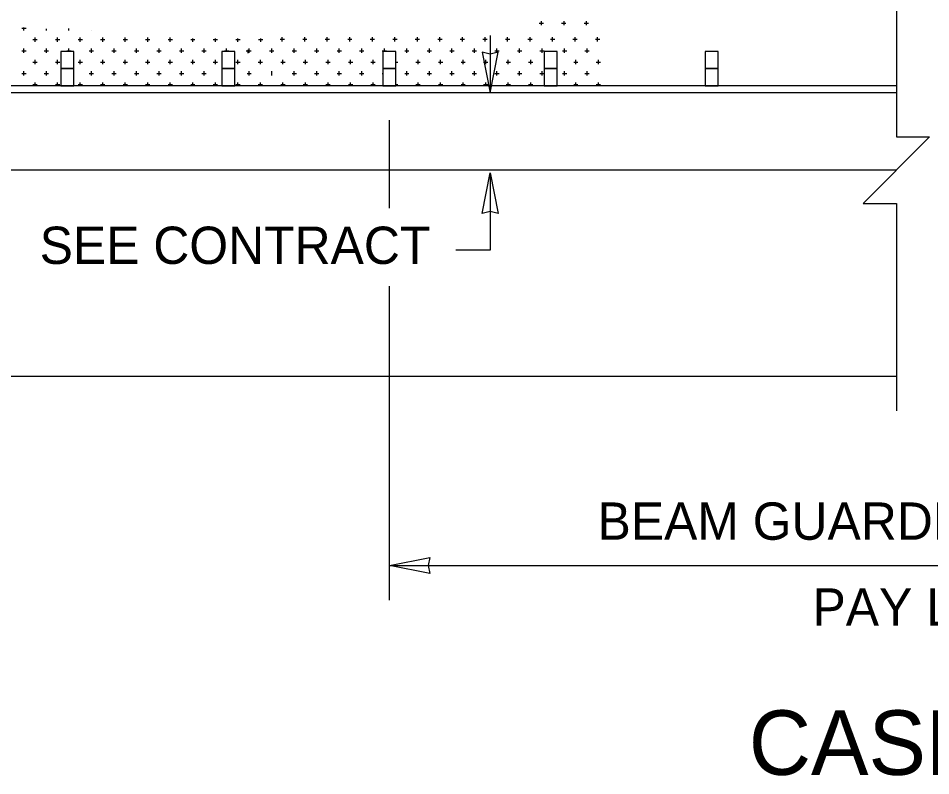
# Model space of a CAD drawing. Extents: x 1312564.5 to 1312581.5, y 1207298.4 to 1207309.4.
# Drawn here: x 1312568.156 to 1312570.114, y 1207305.016 to 1207306.641 of the extents above; entities that cross this region are included whole.
import ezdxf

# ---------------------------------------------------------------- set-up
doc = ezdxf.new("R2010")
doc.units = 0
for name, color, linetype in [('Level 1', 7, 'Continuous'), ('Level 15', 7, 'Continuous'), ('Level 2', 7, 'Continuous'), ('Level 20', 7, 'Continuous'), ('Level 3', 7, 'Continuous'), ('Level 4', 7, 'Continuous'), ('Level 44', 7, 'Continuous')]:
    doc.layers.add(name, color=color, linetype=linetype)

msp = doc.modelspace()

# ---------------------------------------------------------------- linework, layer by layer
at = {"layer": 'Level 15'}
for p, q in [((1312569.1684, 1207306.6036), (1312569.1684, 1207306.4809)), ((1312569.1684, 1207306.309), (1312569.1684, 1207306.1431)), ((1312569.1684, 1207306.1431), (1312569.0946, 1207306.1431))]:
    msp.add_line(p, q, dxfattribs=at)
for points in [[(1312570.0398, 1207306.8953), (1312570.0398, 1207306.3861), (1312570.1112, 1207306.3861), (1312569.9685, 1207306.2434), (1312570.0398, 1207306.2434), (1312570.0398, 1207305.7986)], [(1312568.9523, 1207306.2332), (1312568.9523, 1207306.4221)], [(1312568.9523, 1207305.3931), (1312568.9523, 1207306.0659)], [(1312568.9523, 1207305.4668), (1312571.2748, 1207305.4668)]]:
    msp.add_lwpolyline(points, dxfattribs=at)
for points in [[(1312569.1684, 1207306.4809), (1312569.1854, 1207306.5679), (1312569.1684, 1207306.5638), (1312569.1513, 1207306.5679)], [(1312569.1684, 1207306.309), (1312569.1854, 1207306.2221), (1312569.1684, 1207306.2261), (1312569.1513, 1207306.2221)], [(1312568.9523, 1207305.4668), (1312569.0393, 1207305.4839), (1312569.0353, 1207305.4668), (1312569.0393, 1207305.4498)]]:
    msp.add_lwpolyline(points, close=True, dxfattribs=at)
at = {"layer": 'Level 2'}
for p, q in [((1312570.0398, 1207306.4959), (1312566.8787, 1207306.4959)), ((1312570.0398, 1207306.4806), (1312566.8787, 1207306.4806))]:
    msp.add_line(p, q, dxfattribs=at)
for points in [[(1312568.2473, 1207306.5327), (1312568.275, 1207306.5327), (1312568.275, 1207306.5696), (1312568.2473, 1207306.5696)], [(1312568.5929, 1207306.5327), (1312568.6206, 1207306.5327), (1312568.6206, 1207306.5696), (1312568.5929, 1207306.5696)], [(1312568.9385, 1207306.5327), (1312568.9662, 1207306.5327), (1312568.9662, 1207306.5696), (1312568.9385, 1207306.5696)], [(1312569.2841, 1207306.5327), (1312569.3118, 1207306.5327), (1312569.3118, 1207306.5696), (1312569.2841, 1207306.5696)], [(1312569.6297, 1207306.5327), (1312569.6574, 1207306.5327), (1312569.6574, 1207306.5696), (1312569.6297, 1207306.5696)], [(1312568.2473, 1207306.4959), (1312568.275, 1207306.4959), (1312568.275, 1207306.5327), (1312568.2473, 1207306.5327)], [(1312568.5929, 1207306.4959), (1312568.6206, 1207306.4959), (1312568.6206, 1207306.5327), (1312568.5929, 1207306.5327)], [(1312568.9385, 1207306.4959), (1312568.9662, 1207306.4959), (1312568.9662, 1207306.5327), (1312568.9385, 1207306.5327)], [(1312569.2841, 1207306.4959), (1312569.3118, 1207306.4959), (1312569.3118, 1207306.5327), (1312569.2841, 1207306.5327)], [(1312569.6297, 1207306.4959), (1312569.6574, 1207306.4959), (1312569.6574, 1207306.5327), (1312569.6297, 1207306.5327)]]:
    msp.add_lwpolyline(points, close=True, dxfattribs=at)
at = {"layer": 'Level 3'}
msp.add_line((1312570.0398, 1207306.3147), (1312565.7882, 1207306.3147), dxfattribs=at)
at = {"layer": 'Level 4'}
for p, q in [((1312569.2734, 1207306.63), (1312569.2826, 1207306.63)), ((1312569.278, 1207306.6346), (1312569.278, 1207306.6254)), ((1312569.3217, 1207306.63), (1312569.3263, 1207306.63)), ((1312569.3263, 1207306.6346), (1312569.3263, 1207306.6254)), ((1312569.3263, 1207306.63), (1312569.3309, 1207306.63)), ((1312569.3701, 1207306.63), (1312569.3793, 1207306.63)), ((1312569.3747, 1207306.6346), (1312569.3747, 1207306.6254)), ((1312568.1635, 1207306.6191), (1312568.1728, 1207306.6191)), ((1312568.1682, 1207306.6145), (1312568.1682, 1207306.6208)), ((1312568.2165, 1207306.6145), (1312568.2165, 1207306.6177)), ((1312568.2648, 1207306.6145), (1312568.2648, 1207306.6185)), ((1312568.3131, 1207306.6145), (1312568.3131, 1207306.6145)), ((1312568.1877, 1207306.5949), (1312568.1923, 1207306.5949)), ((1312568.1923, 1207306.5903), (1312568.1923, 1207306.5995)), ((1312568.1923, 1207306.5949), (1312568.1969, 1207306.5949)), ((1312568.236, 1207306.5949), (1312568.2452, 1207306.5949)), ((1312568.2406, 1207306.5903), (1312568.2406, 1207306.5995)), ((1312568.2844, 1207306.5949), (1312568.2936, 1207306.5949)), ((1312568.289, 1207306.5903), (1312568.289, 1207306.5995)), ((1312568.3327, 1207306.5949), (1312568.3419, 1207306.5949)), ((1312568.3373, 1207306.5903), (1312568.3373, 1207306.5995)), ((1312568.381, 1207306.5949), (1312568.3902, 1207306.5949)), ((1312568.3856, 1207306.5903), (1312568.3856, 1207306.5995)), ((1312568.4293, 1207306.5949), (1312568.4386, 1207306.5949)), ((1312568.4339, 1207306.5903), (1312568.4339, 1207306.5995)), ((1312568.4777, 1207306.5949), (1312568.4823, 1207306.5949)), ((1312568.4823, 1207306.5903), (1312568.4823, 1207306.5995)), ((1312568.4823, 1207306.5949), (1312568.4869, 1207306.5949)), ((1312568.526, 1207306.5949), (1312568.5352, 1207306.5949)), ((1312568.5306, 1207306.5903), (1312568.5306, 1207306.5971)), ((1312568.5743, 1207306.5949), (1312568.5835, 1207306.5949)), ((1312568.5789, 1207306.5903), (1312568.5789, 1207306.5971)), ((1312568.6226, 1207306.5949), (1312568.6319, 1207306.5949)), ((1312568.6273, 1207306.5903), (1312568.6273, 1207306.5971)), ((1312568.6714, 1207306.5949), (1312568.6807, 1207306.5949)), ((1312568.6761, 1207306.5903), (1312568.6761, 1207306.5971)), ((1312568.7178, 1207306.5955), (1312568.727, 1207306.5955)), ((1312568.7224, 1207306.5909), (1312568.7224, 1207306.6001)), ((1312568.7662, 1207306.5955), (1312568.7754, 1207306.5955)), ((1312568.7708, 1207306.5909), (1312568.7708, 1207306.6001)), ((1312568.8145, 1207306.5955), (1312568.8237, 1207306.5955)), ((1312568.8191, 1207306.5909), (1312568.8191, 1207306.6001)), ((1312568.8628, 1207306.5955), (1312568.872, 1207306.5955)), ((1312568.8674, 1207306.5909), (1312568.8674, 1207306.6001)), ((1312568.9111, 1207306.5955), (1312568.9203, 1207306.5955)), ((1312568.9157, 1207306.5909), (1312568.9157, 1207306.6001)), ((1312568.9595, 1207306.5955), (1312568.9687, 1207306.5955)), ((1312568.9641, 1207306.5909), (1312568.9641, 1207306.6001)), ((1312569.0078, 1207306.5955), (1312569.017, 1207306.5955)), ((1312569.0124, 1207306.5909), (1312569.0124, 1207306.6001)), ((1312569.0561, 1207306.5955), (1312569.0653, 1207306.5955)), ((1312569.0607, 1207306.5909), (1312569.0607, 1207306.6001)), ((1312569.1044, 1207306.5955), (1312569.1137, 1207306.5955)), ((1312569.109, 1207306.5909), (1312569.109, 1207306.6001)), ((1312569.1528, 1207306.5955), (1312569.162, 1207306.5955)), ((1312569.1574, 1207306.5909), (1312569.1574, 1207306.6001)), ((1312569.2011, 1207306.5955), (1312569.2103, 1207306.5955)), ((1312569.2057, 1207306.5909), (1312569.2057, 1207306.6001)), ((1312569.2494, 1207306.5955), (1312569.2586, 1207306.5955)), ((1312569.254, 1207306.5909), (1312569.254, 1207306.6001)), ((1312569.2978, 1207306.5955), (1312569.307, 1207306.5955)), ((1312569.3024, 1207306.5909), (1312569.3024, 1207306.6001)), ((1312569.3461, 1207306.5955), (1312569.3553, 1207306.5955)), ((1312569.3507, 1207306.5909), (1312569.3507, 1207306.6001)), ((1312569.3944, 1207306.5955), (1312569.4036, 1207306.5955)), ((1312569.399, 1207306.5909), (1312569.399, 1207306.6001)), ((1312568.1635, 1207306.5708), (1312568.1728, 1207306.5708)), ((1312568.1682, 1207306.5662), (1312568.1682, 1207306.5754)), ((1312568.2119, 1207306.5708), (1312568.2211, 1207306.5708)), ((1312568.2165, 1207306.5662), (1312568.2165, 1207306.5754)), ((1312568.2602, 1207306.5708), (1312568.2694, 1207306.5708)), ((1312568.2648, 1207306.5696), (1312568.2648, 1207306.5754)), ((1312568.3085, 1207306.5708), (1312568.3177, 1207306.5708)), ((1312568.3131, 1207306.5662), (1312568.3131, 1207306.5754)), ((1312568.3568, 1207306.5708), (1312568.3661, 1207306.5708)), ((1312568.3615, 1207306.5662), (1312568.3615, 1207306.5754)), ((1312568.4052, 1207306.5708), (1312568.4144, 1207306.5708)), ((1312568.4098, 1207306.5662), (1312568.4098, 1207306.5754)), ((1312568.4535, 1207306.5708), (1312568.4627, 1207306.5708)), ((1312568.4581, 1207306.5662), (1312568.4581, 1207306.5754)), ((1312568.5018, 1207306.5708), (1312568.511, 1207306.5708)), ((1312568.5064, 1207306.5662), (1312568.5064, 1207306.5754)), ((1312568.5502, 1207306.5708), (1312568.5594, 1207306.5708)), ((1312568.5548, 1207306.5662), (1312568.5548, 1207306.5754)), ((1312568.5985, 1207306.5708), (1312568.6077, 1207306.5708)), ((1312568.6031, 1207306.5696), (1312568.6031, 1207306.5754)), ((1312568.645, 1207306.5705), (1312568.6542, 1207306.5705)), ((1312568.6468, 1207306.5708), (1312568.656, 1207306.5708)), ((1312568.6496, 1207306.5659), (1312568.6496, 1207306.5727)), ((1312568.6514, 1207306.5662), (1312568.6514, 1207306.5754)), ((1312568.6951, 1207306.5708), (1312568.7044, 1207306.5708)), ((1312568.6997, 1207306.5662), (1312568.6997, 1207306.5754)), ((1312568.7435, 1207306.5708), (1312568.7527, 1207306.5708)), ((1312568.7481, 1207306.5662), (1312568.7481, 1207306.5754)), ((1312568.7918, 1207306.5708), (1312568.801, 1207306.5708)), ((1312568.7964, 1207306.5662), (1312568.7964, 1207306.5754)), ((1312568.8401, 1207306.5708), (1312568.8493, 1207306.5708)), ((1312568.8447, 1207306.5662), (1312568.8447, 1207306.5754)), ((1312568.8884, 1207306.5708), (1312568.8977, 1207306.5708)), ((1312568.8931, 1207306.5662), (1312568.8931, 1207306.5754)), ((1312568.9368, 1207306.5708), (1312568.946, 1207306.5708)), ((1312568.9414, 1207306.5696), (1312568.9414, 1207306.5754)), ((1312568.9851, 1207306.5708), (1312568.9943, 1207306.5708)), ((1312568.9897, 1207306.5662), (1312568.9897, 1207306.5754)), ((1312569.0334, 1207306.5708), (1312569.0426, 1207306.5708)), ((1312569.038, 1207306.5662), (1312569.038, 1207306.5754)), ((1312569.0818, 1207306.5708), (1312569.091, 1207306.5708)), ((1312569.0864, 1207306.5662), (1312569.0864, 1207306.5754)), ((1312569.1301, 1207306.5708), (1312569.1393, 1207306.5708)), ((1312569.1347, 1207306.5662), (1312569.1347, 1207306.5754)), ((1312569.1784, 1207306.5708), (1312569.1876, 1207306.5708)), ((1312569.183, 1207306.5662), (1312569.183, 1207306.5754)), ((1312569.2267, 1207306.5708), (1312569.236, 1207306.5708)), ((1312569.2313, 1207306.5662), (1312569.2313, 1207306.5754)), ((1312569.2751, 1207306.5708), (1312569.2843, 1207306.5708)), ((1312569.2797, 1207306.5662), (1312569.2797, 1207306.5754)), ((1312569.3234, 1207306.5708), (1312569.3326, 1207306.5708)), ((1312569.328, 1207306.5662), (1312569.328, 1207306.5754)), ((1312569.3717, 1207306.5708), (1312569.3809, 1207306.5708)), ((1312569.3763, 1207306.5662), (1312569.3763, 1207306.5754)), ((1312568.1923, 1207306.542), (1312568.1923, 1207306.5512)), ((1312568.2406, 1207306.542), (1312568.2406, 1207306.5512)), ((1312568.289, 1207306.542), (1312568.289, 1207306.5512)), ((1312568.3373, 1207306.542), (1312568.3373, 1207306.5512)), ((1312568.3856, 1207306.542), (1312568.3856, 1207306.5512)), ((1312568.4339, 1207306.542), (1312568.4339, 1207306.5512)), ((1312568.4823, 1207306.542), (1312568.4823, 1207306.5512)), ((1312568.5306, 1207306.542), (1312568.5306, 1207306.5512)), ((1312568.5789, 1207306.542), (1312568.5789, 1207306.5512)), ((1312568.6273, 1207306.542), (1312568.6273, 1207306.5512)), ((1312568.6756, 1207306.542), (1312568.6756, 1207306.5512)), ((1312568.7239, 1207306.542), (1312568.7239, 1207306.5512)), ((1312568.7722, 1207306.542), (1312568.7722, 1207306.5512)), ((1312568.8206, 1207306.542), (1312568.8206, 1207306.5512)), ((1312568.8689, 1207306.542), (1312568.8689, 1207306.5512)), ((1312568.9172, 1207306.542), (1312568.9172, 1207306.5512)), ((1312569.0139, 1207306.542), (1312569.0139, 1207306.5512)), ((1312569.0622, 1207306.542), (1312569.0622, 1207306.5512)), ((1312569.1105, 1207306.542), (1312569.1105, 1207306.5512)), ((1312569.1589, 1207306.542), (1312569.1589, 1207306.5512)), ((1312569.2072, 1207306.542), (1312569.2072, 1207306.5512)), ((1312569.2555, 1207306.542), (1312569.2555, 1207306.5512)), ((1312569.3522, 1207306.542), (1312569.3522, 1207306.5512)), ((1312569.4005, 1207306.542), (1312569.4005, 1207306.5512)), ((1312568.1877, 1207306.5466), (1312568.1923, 1207306.5466)), ((1312568.1923, 1207306.5466), (1312568.1969, 1207306.5466)), ((1312568.236, 1207306.5466), (1312568.2452, 1207306.5466)), ((1312568.2844, 1207306.5466), (1312568.2936, 1207306.5466)), ((1312568.3327, 1207306.5466), (1312568.3419, 1207306.5466)), ((1312568.381, 1207306.5466), (1312568.3902, 1207306.5466)), ((1312568.4293, 1207306.5466), (1312568.4386, 1207306.5466)), ((1312568.4777, 1207306.5466), (1312568.4823, 1207306.5466)), ((1312568.4823, 1207306.5466), (1312568.4869, 1207306.5466)), ((1312568.526, 1207306.5466), (1312568.5352, 1207306.5466)), ((1312568.5743, 1207306.5466), (1312568.5835, 1207306.5466)), ((1312568.6226, 1207306.5466), (1312568.6319, 1207306.5466)), ((1312568.671, 1207306.5466), (1312568.6802, 1207306.5466)), ((1312568.7193, 1207306.5466), (1312568.7285, 1207306.5466)), ((1312568.7676, 1207306.5466), (1312568.7722, 1207306.5466)), ((1312568.7722, 1207306.5466), (1312568.7768, 1207306.5466)), ((1312568.816, 1207306.5466), (1312568.8252, 1207306.5466)), ((1312568.8643, 1207306.5466), (1312568.8735, 1207306.5466)), ((1312568.9126, 1207306.5466), (1312568.9218, 1207306.5466)), ((1312568.9662, 1207306.5466), (1312568.9702, 1207306.5466)), ((1312569.0093, 1207306.5466), (1312569.0185, 1207306.5466)), ((1312569.0576, 1207306.5466), (1312569.0622, 1207306.5466)), ((1312569.0622, 1207306.5466), (1312569.0668, 1207306.5466)), ((1312569.1059, 1207306.5466), (1312569.1151, 1207306.5466)), ((1312569.1542, 1207306.5466), (1312569.1635, 1207306.5466)), ((1312569.2026, 1207306.5466), (1312569.2118, 1207306.5466)), ((1312569.2509, 1207306.5466), (1312569.2601, 1207306.5466)), ((1312569.3476, 1207306.5466), (1312569.3522, 1207306.5466)), ((1312569.3522, 1207306.5466), (1312569.3568, 1207306.5466)), ((1312569.3959, 1207306.5466), (1312569.4051, 1207306.5466)), ((1312568.1635, 1207306.5224), (1312568.1728, 1207306.5224)), ((1312568.1682, 1207306.5178), (1312568.1682, 1207306.527)), ((1312568.2119, 1207306.5224), (1312568.2211, 1207306.5224)), ((1312568.2165, 1207306.5178), (1312568.2165, 1207306.527)), ((1312568.3085, 1207306.5224), (1312568.3177, 1207306.5224)), ((1312568.3131, 1207306.5178), (1312568.3131, 1207306.527)), ((1312568.3568, 1207306.5224), (1312568.3661, 1207306.5224)), ((1312568.3615, 1207306.5178), (1312568.3615, 1207306.527)), ((1312568.4052, 1207306.5224), (1312568.4144, 1207306.5224)), ((1312568.4098, 1207306.5178), (1312568.4098, 1207306.527)), ((1312568.4535, 1207306.5224), (1312568.4627, 1207306.5224)), ((1312568.4581, 1207306.5178), (1312568.4581, 1207306.527)), ((1312568.5018, 1207306.5224), (1312568.511, 1207306.5224)), ((1312568.5064, 1207306.5178), (1312568.5064, 1207306.527)), ((1312568.5502, 1207306.5224), (1312568.5594, 1207306.5224)), ((1312568.5548, 1207306.5178), (1312568.5548, 1207306.527)), ((1312568.6468, 1207306.5224), (1312568.656, 1207306.5224)), ((1312568.6514, 1207306.5178), (1312568.6514, 1207306.527)), ((1312568.6997, 1207306.5178), (1312568.6997, 1207306.527)), ((1312568.7435, 1207306.5224), (1312568.7527, 1207306.5224)), ((1312568.7481, 1207306.5178), (1312568.7481, 1207306.527)), ((1312568.7918, 1207306.5224), (1312568.801, 1207306.5224)), ((1312568.7964, 1207306.5178), (1312568.7964, 1207306.527)), ((1312568.8401, 1207306.5224), (1312568.8493, 1207306.5224)), ((1312568.8447, 1207306.5178), (1312568.8447, 1207306.527)), ((1312568.8884, 1207306.5224), (1312568.8977, 1207306.5224)), ((1312568.8931, 1207306.5178), (1312568.8931, 1207306.527)), ((1312568.9368, 1207306.5224), (1312568.9385, 1207306.5224)), ((1312568.9851, 1207306.5224), (1312568.9943, 1207306.5224)), ((1312568.9897, 1207306.5178), (1312568.9897, 1207306.527)), ((1312569.0334, 1207306.5224), (1312569.0426, 1207306.5224)), ((1312569.038, 1207306.5178), (1312569.038, 1207306.527)), ((1312569.0818, 1207306.5224), (1312569.091, 1207306.5224)), ((1312569.0864, 1207306.5178), (1312569.0864, 1207306.527)), ((1312569.1301, 1207306.5224), (1312569.1393, 1207306.5224)), ((1312569.1347, 1207306.5178), (1312569.1347, 1207306.527)), ((1312569.1784, 1207306.5224), (1312569.1876, 1207306.5224)), ((1312569.183, 1207306.5178), (1312569.183, 1207306.527)), ((1312569.2267, 1207306.5224), (1312569.236, 1207306.5224)), ((1312569.2313, 1207306.5178), (1312569.2313, 1207306.527)), ((1312569.2751, 1207306.5224), (1312569.2841, 1207306.5224)), ((1312569.2797, 1207306.5178), (1312569.2797, 1207306.527)), ((1312569.3234, 1207306.5224), (1312569.3326, 1207306.5224)), ((1312569.328, 1207306.5178), (1312569.328, 1207306.527)), ((1312569.3717, 1207306.5224), (1312569.3809, 1207306.5224)), ((1312569.3763, 1207306.5178), (1312569.3763, 1207306.527)), ((1312568.1877, 1207306.4983), (1312568.1923, 1207306.4983)), ((1312568.1923, 1207306.4959), (1312568.1923, 1207306.5029)), ((1312568.1923, 1207306.4983), (1312568.1969, 1207306.4983)), ((1312568.236, 1207306.4983), (1312568.2452, 1207306.4983)), ((1312568.2406, 1207306.4959), (1312568.2406, 1207306.5029)), ((1312568.2844, 1207306.4983), (1312568.2936, 1207306.4983)), ((1312568.289, 1207306.4959), (1312568.289, 1207306.5029)), ((1312568.3327, 1207306.4983), (1312568.3419, 1207306.4983)), ((1312568.3373, 1207306.4959), (1312568.3373, 1207306.5029)), ((1312568.381, 1207306.4983), (1312568.3902, 1207306.4983)), ((1312568.3856, 1207306.4959), (1312568.3856, 1207306.5029)), ((1312568.4293, 1207306.4983), (1312568.4386, 1207306.4983)), ((1312568.4339, 1207306.4959), (1312568.4339, 1207306.5029)), ((1312568.4777, 1207306.4983), (1312568.4823, 1207306.4983)), ((1312568.4823, 1207306.4959), (1312568.4823, 1207306.5029)), ((1312568.4823, 1207306.4983), (1312568.4869, 1207306.4983)), ((1312568.526, 1207306.4983), (1312568.5352, 1207306.4983)), ((1312568.5306, 1207306.4959), (1312568.5306, 1207306.5029)), ((1312568.5743, 1207306.4983), (1312568.5835, 1207306.4983)), ((1312568.5789, 1207306.4959), (1312568.5789, 1207306.5029)), ((1312568.6226, 1207306.4983), (1312568.6319, 1207306.4983)), ((1312568.6273, 1207306.4959), (1312568.6273, 1207306.5029)), ((1312568.671, 1207306.4983), (1312568.6802, 1207306.4983)), ((1312568.6756, 1207306.4959), (1312568.6756, 1207306.5029)), ((1312568.7193, 1207306.4983), (1312568.7285, 1207306.4983)), ((1312568.7239, 1207306.4959), (1312568.7239, 1207306.5029)), ((1312568.7676, 1207306.4983), (1312568.7722, 1207306.4983)), ((1312568.7722, 1207306.4959), (1312568.7722, 1207306.5029)), ((1312568.7722, 1207306.4983), (1312568.7768, 1207306.4983)), ((1312568.816, 1207306.4983), (1312568.8252, 1207306.4983)), ((1312568.8206, 1207306.4959), (1312568.8206, 1207306.5029)), ((1312568.8643, 1207306.4983), (1312568.8735, 1207306.4983)), ((1312568.8689, 1207306.4959), (1312568.8689, 1207306.5029)), ((1312568.9126, 1207306.4983), (1312568.9218, 1207306.4983)), ((1312568.9172, 1207306.4959), (1312568.9172, 1207306.5029)), ((1312568.9662, 1207306.4983), (1312568.9702, 1207306.4983)), ((1312569.0093, 1207306.4983), (1312569.0185, 1207306.4983)), ((1312569.0139, 1207306.4959), (1312569.0139, 1207306.5029)), ((1312569.0576, 1207306.4983), (1312569.0622, 1207306.4983)), ((1312569.0622, 1207306.4959), (1312569.0622, 1207306.5029)), ((1312569.0622, 1207306.4983), (1312569.0668, 1207306.4983)), ((1312569.1059, 1207306.4983), (1312569.1151, 1207306.4983)), ((1312569.1105, 1207306.4959), (1312569.1105, 1207306.5029)), ((1312569.1542, 1207306.4983), (1312569.1635, 1207306.4983)), ((1312569.1589, 1207306.4959), (1312569.1589, 1207306.5029)), ((1312569.2026, 1207306.4983), (1312569.2118, 1207306.4983)), ((1312569.2072, 1207306.4959), (1312569.2072, 1207306.5029)), ((1312569.2509, 1207306.4983), (1312569.2601, 1207306.4983)), ((1312569.2555, 1207306.4959), (1312569.2555, 1207306.5029)), ((1312569.3476, 1207306.4983), (1312569.3522, 1207306.4983)), ((1312569.3522, 1207306.4959), (1312569.3522, 1207306.5029)), ((1312569.3522, 1207306.4983), (1312569.3568, 1207306.4983)), ((1312569.3959, 1207306.4983), (1312569.4051, 1207306.4983)), ((1312569.4005, 1207306.4959), (1312569.4005, 1207306.5029))]:
    msp.add_line(p, q, dxfattribs=at)
at = {"layer": 'Level 44'}
msp.add_line((1312570.0398, 1207305.8723), (1312565.7882, 1207305.8723), dxfattribs=at)

# ---------------------------------------------------------------- texts
at = {"layer": 'Level 1'}
msp.add_text('CASE 9A', height=0.13824, dxfattribs=at).set_placement((1312569.7232, 1207305.0182))
at = {"layer": 'Level 20'}
for s, p in [('SEE CONTRACT', (1312568.202, 1207306.1137)), ('BEAM GUARDRAIL TYPE 10', (1312569.3988, 1207305.5223)), ('PAY LIMIT', (1312569.8599, 1207305.338))]:
    msp.add_text(s, height=0.08, dxfattribs=at).set_placement(p)

doc.saveas('drawing.dxf')
